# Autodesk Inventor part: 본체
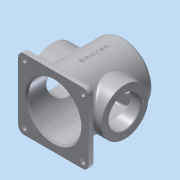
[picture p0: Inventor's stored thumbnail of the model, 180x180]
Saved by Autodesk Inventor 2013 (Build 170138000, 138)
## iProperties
Created: 2015-10
Part Number: 본체
Material: 알루미늄 6061
Document SubType Name: Modeling
Designer: Administrator
Density: 2.71 g/cm^3
Mass: 987.032 g
Surface Area: 1039.63 cm^2
Volume: 364.218 cm^3
Author: Administrator
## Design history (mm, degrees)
sketch "스케치1"
  geometry: L1 (-60, 60)-(60, 60); L2 (60, 60)-(60, -60); L3 (60, -60)-(-60, -60); L4 (-60, -60)-(-60, 60); 1 further point
  constraints: 8 end point, 2 parallel, 1 horizontal, 1 perpendicular
  dimensions: "d0" = 120 distance of L1.start L1.end; "d2" = 120 distance of L3.end L1.start
extrude "돌출1" new body sketch "스케치1" distance "d3" = 10; taper "d4" = 0 deg
sketch "스케치2"
  geometry: C1 r 50 at (0, 0); 1 further point
  constraints: 1 centre point, 1 coincident
  dimensions: "d5" = 100 diameter of C1
extrude "돌출2" join sketch "스케치2" distance "d7" = 110; taper "d8" = 0 deg
sketch "스케치3"
  geometry: C1 r 50 at (0, 0) reference; C2 r 40 at (0, 0)
  constraints: 1 centre point, 1 coincident
  dimensions: "d9" = 80 diameter of C2
extrude "돌출3" join sketch "스케치3" distance "d11" = 5; taper "d12" = 0 deg
sketch "스케치4"
  geometry: C1 r 40 at (0, 0) reference; C2 r 27 at (0, 0)
  constraints: 1 centre point, 1 coincident
  dimensions: "d13" = 54 diameter of C2
extrude "돌출4" cut sketch "스케치4" distance "d15" = 13; taper "d16" = 0 deg
sketch "스케치5"
  geometry: C1 r 45 at (0, 0); 1 further point
  constraints: 1 centre point, 1 coincident
  dimensions: "d17" = 90 diameter of C1
extrude "돌출5" cut sketch "스케치5" distance "d19" = 112; taper "d20" = 0 deg
node "작업 평면1"
sketch "스케치6"
  geometry: L1 (0, 0)-(60, 0); C1 r 40 at (60, 0)
  constraints: 2 end point, 1 centre point, 1 coincident, 1 horizontal
  dimensions: "d22" = 60 distance of L1.start L1.end; "d23" = 80 diameter of C1
extrude "돌출6" join sketch "스케치6" stored distance "d24" = 112; taper "d25" = 0 deg
node "작업 평면2"
sketch "스케치7"
  geometry: L1 (0, 0)-(60, 0); C1 r 40 at (60, 0)
  constraints: 2 end point, 1 centre point, 1 coincident, 1 horizontal
  dimensions: "d27" = 60 distance of L1.start L1.end
extrude "돌출7" join sketch "스케치7" stored distance "d29" = 112; taper "d30" = 0 deg
sketch "스케치8"
  geometry: C1 r 40 at (0, 0) reference; C2 r 27 at (0, 0); 1 further point
  constraints: 1 centre point, 1 coincident
  dimensions: "d31" = 54 diameter of C2
extrude "돌출8" cut sketch "스케치8" stored distance "d33" = 112; taper "d34" = 0 deg
sketch "스케치9"
  geometry: C1 r 40 at (0, 0) reference; C2 r 27 at (0, 0); 1 further point
  constraints: 1 centre point, 1 coincident
  dimensions: "d35" = 54 diameter of C2
extrude "돌출9" cut sketch "스케치9" stored distance "d37" = 112; taper "d38" = 0 deg
sketch "스케치10"
  geometry: C1 r 4 at (-50, 50); C2 r 4 at (50, 50); C3 r 4 at (50, -50); C4 r 4 at (-50, -50)
  constraints: 4 centre point
  dimensions: "d44" = 4 radius of C1; "d45" = 4 radius of C2; "d46" = 4 radius of C3; "d47" = 4 radius of C4
extrude "돌출10" cut sketch "스케치10" stored distance "d48" = 112; taper "d49" = 0 deg
sketch "스케치11"
  geometry: 6 further points
  constraints: 1 coincident
hole "구멍1" sketch "스케치11" at (0, 32.5), (-32.5, 0), (32.5, 0), (0, -32.5) diameter "d51" = 3.242; stored, may be unused: countersink angle "d55" = 82 deg, drill point angle "d57" = 118 deg; dims "d52" = 8, "d53" = 3.023, "d54" = 2, "d56" = 10
sketch "스케치12"
  geometry: 5 further points
hole "구멍2" sketch "스케치12" at (0, 32.5), (-32.5, 0), (0, -32.5), (32.5, 0) diameter "d60" = 3.242; stored, may be unused: countersink angle "d64" = 82 deg, drill point angle "d66" = 118 deg; dims "d61" = 8, "d62" = 3.023, "d63" = 2, "d65" = 10
sketch "스케치13"
  geometry: 4 further points
hole "구멍3" sketch "스케치13" at (-22.981, 22.981), (-22.981, -22.981), (22.981, -22.981), (22.981, 22.981) diameter "d70" = 3.242; stored, may be unused: countersink angle "d74" = 82 deg, drill point angle "d76" = 118 deg; dims "d71" = 8, "d72" = 3.023, "d73" = 2, "d75" = 10
chamfer "모따기1" distance "d77" = 3; stored, may be unused: second distance "d78" = 2, angle "d79" = 45 deg
fillet "모깎기1" dims "d80" = 3, "d81" = 5, "d82" = 3
fillet "모깎기3" dims "d84" = 10, "d85" = 3
chamfer "모따기2" distance "d86" = 1; stored, may be unused: second distance "d87" = 2, angle "d88" = 45 deg
chamfer "모따기3" distance "d89" = 1; stored, may be unused: second distance "d90" = 2, angle "d91" = 45 deg
chamfer "모따기4" distance "d92" = 1; stored, may be unused: second distance "d93" = 2, angle "d94" = 45 deg
node "작업 평면4"
sketch "스케치15"
  geometry: 2 further points
  constraints: 1 other
feature "엠보싱1" sketch "스케치15" dims "d0" = 120, "d2" = 120, "d13" = 54, "d99" = 0.5, "d100" = 0
node "솔리드1"
other parameters: "d21" = 62, "d26" = -62
